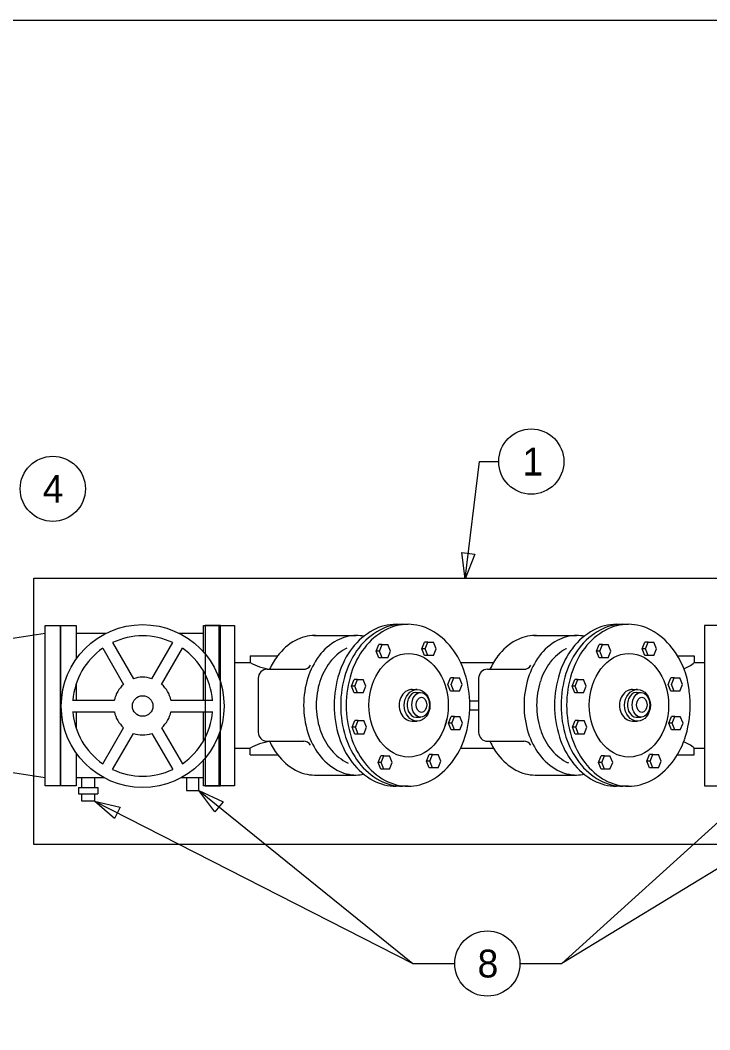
# Model space of a CAD drawing. Extents: x 10291.2 to 10382.2, y 10083.1 to 10135.3.
# Drawn here: x 10345.72 to 10363.56, y 10109.18 to 10135.29 of the extents above; entities that cross this region are included whole.
import ezdxf

# ---------------------------------------------------------------- set-up
doc = ezdxf.new("R2010")
doc.units = 0
for name, color, linetype in [('G-ANNO-NPLT', 7, 'Continuous'), ('G-ANNO-SYMB', 7, 'Continuous'), ('G-DETL-LINE', 7, 'Continuous'), ('G-DETL-TEXT', 7, 'Continuous')]:
    doc.layers.add(name, color=color, linetype=linetype)

msp = doc.modelspace()

# ---------------------------------------------------------------- linework, layer by layer
at = {"layer": 'G-ANNO-NPLT'}
msp.add_lwpolyline([(10336.657, 10086.15), (10336.657, 10135.292), (10382.157, 10135.292), (10382.157, 10086.15)], close=True, dxfattribs=at)
at = {"layer": 'G-ANNO-SYMB'}
for centre in [(10358.941, 10123.878), (10346.562, 10123.174), (10357.804, 10110.897)]:
    msp.add_circle(centre, 0.843, dxfattribs=at)
at = {"layer": 'G-DETL-LINE'}
for p, q in [((10355.441, 10119.67), (10355.753, 10119.67)), ((10361.142, 10119.67), (10361.453, 10119.67)), ((10363.422, 10119.612), (10363.422, 10117.576)), ((10346.364, 10119.436), (10344.045, 10119.066)), ((10347.94, 10119.436), (10347.165, 10119.436)), ((10350.463, 10119.436), (10349.833, 10119.436)), ((10353.303, 10119.379), (10354.412, 10119.379)), ((10359.004, 10119.379), (10360.113, 10119.379)), ((10348.106, 10119.201), (10348.647, 10118.264)), ((10349.126, 10118.264), (10349.667, 10119.201)), ((10354.928, 10118.974), (10354.997, 10119.148)), ((10355.081, 10119.148), (10354.997, 10119.148)), ((10355.012, 10118.974), (10355.081, 10119.148)), ((10355.081, 10119.148), (10355.226, 10119.148)), ((10355.296, 10118.974), (10355.226, 10119.148)), ((10356.11, 10119.035), (10356.18, 10119.209)), ((10356.264, 10119.209), (10356.18, 10119.209)), ((10356.195, 10119.035), (10356.264, 10119.209)), ((10356.264, 10119.209), (10356.409, 10119.209)), ((10356.479, 10119.035), (10356.409, 10119.209)), ((10360.628, 10118.974), (10360.698, 10119.148)), ((10360.782, 10119.148), (10360.698, 10119.148)), ((10360.713, 10118.974), (10360.782, 10119.148)), ((10360.782, 10119.148), (10360.927, 10119.148)), ((10360.997, 10118.974), (10360.927, 10119.148)), ((10361.811, 10119.035), (10361.88, 10119.209)), ((10361.964, 10119.209), (10361.88, 10119.209)), ((10361.895, 10119.035), (10361.964, 10119.209)), ((10361.964, 10119.209), (10362.109, 10119.209)), ((10362.18, 10119.035), (10362.109, 10119.209)), ((10347.853, 10119.054), (10348.394, 10118.117)), ((10349.379, 10118.117), (10349.92, 10119.054)), ((10351.667, 10118.856), (10352.38, 10118.856)), ((10351.667, 10118.856), (10351.667, 10118.681)), ((10355.012, 10118.974), (10354.928, 10118.974)), ((10354.997, 10118.8), (10354.928, 10118.974)), ((10355.081, 10118.8), (10355.012, 10118.974)), ((10355.226, 10118.799), (10355.296, 10118.974)), ((10356.195, 10119.035), (10356.11, 10119.035)), ((10356.18, 10118.861), (10356.11, 10119.035)), ((10356.264, 10118.861), (10356.18, 10118.861)), ((10356.264, 10118.861), (10356.195, 10119.035)), ((10356.409, 10118.86), (10356.264, 10118.861)), ((10356.409, 10118.86), (10356.479, 10119.035)), ((10360.698, 10118.8), (10360.628, 10118.974)), ((10360.713, 10118.974), (10360.628, 10118.974)), ((10360.782, 10118.8), (10360.713, 10118.974)), ((10360.927, 10118.799), (10360.997, 10118.974)), ((10361.88, 10118.861), (10361.811, 10119.035)), ((10361.895, 10119.035), (10361.811, 10119.035)), ((10361.964, 10118.861), (10361.88, 10118.861)), ((10361.964, 10118.861), (10361.895, 10119.035)), ((10362.109, 10118.86), (10361.964, 10118.861)), ((10362.109, 10118.86), (10362.18, 10119.035)), ((10362.718, 10118.856), (10363.154, 10118.856)), ((10362.72, 10118.856), (10363.155, 10118.856)), ((10363.154, 10118.856), (10363.154, 10118.682)), ((10363.155, 10118.856), (10363.155, 10118.681)), ((10351.265, 10118.681), (10351.667, 10118.681)), ((10355.081, 10118.8), (10354.997, 10118.8)), ((10355.226, 10118.799), (10355.081, 10118.8)), ((10357.113, 10118.681), (10357.963, 10118.681)), ((10360.782, 10118.8), (10360.698, 10118.8)), ((10360.927, 10118.799), (10360.782, 10118.799)), ((10363.155, 10118.681), (10363.422, 10118.681)), ((10352.111, 10118.507), (10353.056, 10118.507)), ((10356.784, 10118.114), (10356.853, 10118.288)), ((10356.937, 10118.288), (10356.853, 10118.288)), ((10356.868, 10118.114), (10356.937, 10118.288)), ((10356.937, 10118.288), (10357.082, 10118.288)), ((10357.152, 10118.114), (10357.082, 10118.288)), ((10357.812, 10118.507), (10358.757, 10118.507)), ((10362.485, 10118.114), (10362.554, 10118.288)), ((10362.638, 10118.288), (10362.554, 10118.288)), ((10362.569, 10118.114), (10362.638, 10118.288)), ((10362.638, 10118.288), (10362.783, 10118.288)), ((10362.853, 10118.114), (10362.783, 10118.288)), ((10351.879, 10118.274), (10351.879, 10116.878)), ((10354.293, 10118.072), (10354.362, 10118.246)), ((10354.362, 10117.897), (10354.293, 10118.072)), ((10354.377, 10118.072), (10354.293, 10118.072)), ((10354.446, 10118.246), (10354.362, 10118.246)), ((10354.377, 10118.072), (10354.446, 10118.246)), ((10354.446, 10117.897), (10354.377, 10118.072)), ((10354.446, 10118.246), (10354.591, 10118.246)), ((10354.662, 10118.072), (10354.591, 10118.246)), ((10354.591, 10117.897), (10354.662, 10118.072)), ((10356.853, 10117.94), (10356.784, 10118.114)), ((10356.937, 10117.94), (10356.868, 10118.114)), ((10357.082, 10117.939), (10357.152, 10118.114)), ((10357.579, 10118.274), (10357.579, 10116.878)), ((10359.994, 10118.072), (10360.063, 10118.246)), ((10360.063, 10117.897), (10359.994, 10118.072)), ((10360.078, 10118.072), (10359.994, 10118.072)), ((10360.147, 10118.246), (10360.063, 10118.246)), ((10360.078, 10118.072), (10360.147, 10118.246)), ((10360.147, 10117.897), (10360.078, 10118.072)), ((10360.147, 10118.246), (10360.292, 10118.246)), ((10360.362, 10118.072), (10360.292, 10118.246)), ((10360.292, 10117.897), (10360.362, 10118.072)), ((10362.554, 10117.94), (10362.485, 10118.114)), ((10362.638, 10117.94), (10362.569, 10118.114)), ((10362.783, 10117.939), (10362.853, 10118.114)), ((10354.446, 10117.897), (10354.362, 10117.897)), ((10354.591, 10117.897), (10354.446, 10117.897)), ((10355.855, 10117.983), (10355.987, 10117.983)), ((10355.955, 10117.907), (10356.078, 10117.907)), ((10356.937, 10117.94), (10356.853, 10117.94)), ((10357.082, 10117.939), (10356.937, 10117.94)), ((10360.147, 10117.897), (10360.063, 10117.897)), ((10360.292, 10117.897), (10360.147, 10117.897)), ((10361.556, 10117.983), (10361.688, 10117.983)), ((10361.655, 10117.907), (10361.779, 10117.907)), ((10362.638, 10117.94), (10362.554, 10117.94)), ((10362.783, 10117.939), (10362.638, 10117.94)), ((10347.072, 10117.706), (10348.155, 10117.706)), ((10349.618, 10117.706), (10350.701, 10117.706)), ((10357.349, 10117.692), (10357.579, 10117.692)), ((10347.072, 10117.407), (10348.155, 10117.407)), ((10349.618, 10117.407), (10350.701, 10117.407)), ((10355.955, 10117.267), (10356.078, 10117.267)), ((10356.797, 10117.115), (10356.866, 10117.289)), ((10356.95, 10117.289), (10356.866, 10117.289)), ((10356.881, 10117.115), (10356.95, 10117.289)), ((10356.95, 10117.289), (10357.095, 10117.289)), ((10357.165, 10117.115), (10357.095, 10117.289)), ((10357.349, 10117.46), (10357.579, 10117.46)), ((10361.655, 10117.267), (10361.779, 10117.267)), ((10362.497, 10117.115), (10362.567, 10117.289)), ((10362.651, 10117.289), (10362.567, 10117.289)), ((10362.582, 10117.115), (10362.651, 10117.289)), ((10362.651, 10117.289), (10362.796, 10117.289)), ((10362.866, 10117.115), (10362.796, 10117.289)), ((10347.853, 10116.059), (10348.394, 10116.996)), ((10349.379, 10116.996), (10349.92, 10116.059)), ((10354.307, 10117.007), (10354.377, 10117.181)), ((10354.392, 10117.007), (10354.307, 10117.007)), ((10354.377, 10116.833), (10354.307, 10117.007)), ((10354.461, 10117.181), (10354.377, 10117.181)), ((10354.392, 10117.007), (10354.461, 10117.181)), ((10354.461, 10116.833), (10354.392, 10117.007)), ((10354.461, 10117.181), (10354.606, 10117.181)), ((10354.676, 10117.007), (10354.606, 10117.181)), ((10354.606, 10116.832), (10354.676, 10117.007)), ((10355.855, 10117.169), (10355.987, 10117.169)), ((10356.881, 10117.115), (10356.797, 10117.115)), ((10356.866, 10116.941), (10356.797, 10117.115)), ((10356.95, 10116.941), (10356.881, 10117.115)), ((10357.095, 10116.94), (10357.165, 10117.115)), ((10360.008, 10117.007), (10360.077, 10117.181)), ((10360.092, 10117.007), (10360.008, 10117.007)), ((10360.077, 10116.833), (10360.008, 10117.007)), ((10360.162, 10117.181), (10360.077, 10117.181)), ((10360.092, 10117.007), (10360.162, 10117.181)), ((10360.162, 10116.833), (10360.092, 10117.007)), ((10360.162, 10117.181), (10360.307, 10117.181)), ((10360.377, 10117.007), (10360.307, 10117.181)), ((10360.307, 10116.832), (10360.377, 10117.007)), ((10361.556, 10117.169), (10361.688, 10117.169)), ((10362.582, 10117.115), (10362.497, 10117.115)), ((10362.567, 10116.941), (10362.497, 10117.115)), ((10362.651, 10116.941), (10362.582, 10117.115)), ((10362.796, 10116.94), (10362.866, 10117.115)), ((10348.106, 10115.912), (10348.647, 10116.849)), ((10349.126, 10116.849), (10349.667, 10115.912)), ((10354.461, 10116.833), (10354.377, 10116.833)), ((10354.606, 10116.832), (10354.461, 10116.833)), ((10356.95, 10116.941), (10356.866, 10116.941)), ((10357.095, 10116.94), (10356.95, 10116.941)), ((10360.162, 10116.833), (10360.077, 10116.833)), ((10360.307, 10116.832), (10360.162, 10116.833)), ((10362.651, 10116.941), (10362.567, 10116.941)), ((10362.796, 10116.94), (10362.651, 10116.941)), ((10351.265, 10116.471), (10351.667, 10116.471)), ((10351.667, 10116.296), (10351.667, 10116.471)), ((10352.111, 10116.645), (10353.056, 10116.645)), ((10357.113, 10116.471), (10357.963, 10116.471)), ((10357.812, 10116.645), (10358.757, 10116.645)), ((10363.155, 10116.296), (10363.155, 10116.471)), ((10363.155, 10116.471), (10363.422, 10116.471)), ((10351.667, 10116.296), (10352.38, 10116.296)), ((10354.977, 10116.097), (10355.046, 10116.271)), ((10355.13, 10116.271), (10355.046, 10116.271)), ((10355.061, 10116.097), (10355.13, 10116.271)), ((10355.13, 10116.271), (10355.275, 10116.27)), ((10355.345, 10116.097), (10355.275, 10116.27)), ((10356.231, 10116.133), (10356.3, 10116.307)), ((10356.384, 10116.307), (10356.3, 10116.307)), ((10356.315, 10116.133), (10356.384, 10116.307)), ((10356.384, 10116.307), (10356.529, 10116.307)), ((10356.599, 10116.133), (10356.529, 10116.307)), ((10360.677, 10116.097), (10360.746, 10116.271)), ((10360.831, 10116.271), (10360.746, 10116.271)), ((10360.762, 10116.097), (10360.831, 10116.271)), ((10360.831, 10116.271), (10360.976, 10116.27)), ((10361.046, 10116.097), (10360.976, 10116.27)), ((10361.932, 10116.133), (10362.001, 10116.307)), ((10362.085, 10116.307), (10362.001, 10116.307)), ((10362.016, 10116.133), (10362.085, 10116.307)), ((10362.085, 10116.307), (10362.23, 10116.307)), ((10362.3, 10116.133), (10362.23, 10116.307)), ((10362.72, 10116.296), (10363.155, 10116.296)), ((10346.364, 10115.696), (10344.045, 10116.066)), ((10355.061, 10116.097), (10354.977, 10116.097)), ((10355.046, 10115.922), (10354.977, 10116.097)), ((10355.13, 10115.922), (10355.061, 10116.097)), ((10355.275, 10115.922), (10355.345, 10116.097)), ((10356.315, 10116.133), (10356.231, 10116.133)), ((10356.3, 10115.959), (10356.231, 10116.133)), ((10356.384, 10115.959), (10356.3, 10115.959)), ((10356.384, 10115.959), (10356.315, 10116.133)), ((10356.529, 10115.958), (10356.384, 10115.959)), ((10356.529, 10115.958), (10356.599, 10116.133)), ((10360.746, 10115.922), (10360.677, 10116.097)), ((10360.762, 10116.097), (10360.677, 10116.097)), ((10360.831, 10115.922), (10360.762, 10116.097)), ((10360.976, 10115.922), (10361.046, 10116.097)), ((10362.001, 10115.959), (10361.932, 10116.133)), ((10362.016, 10116.133), (10361.932, 10116.133)), ((10362.085, 10115.959), (10362.001, 10115.959)), ((10362.085, 10115.959), (10362.016, 10116.133)), ((10362.23, 10115.958), (10362.085, 10115.959)), ((10362.23, 10115.958), (10362.3, 10116.133)), ((10347.903, 10115.696), (10347.165, 10115.696)), ((10347.314, 10115.453), (10347.314, 10115.696)), ((10347.64, 10115.696), (10347.64, 10115.453)), ((10350.463, 10115.696), (10349.871, 10115.696)), ((10350.019, 10115.696), (10350.019, 10115.37)), ((10350.344, 10115.37), (10350.344, 10115.696)), ((10353.337, 10115.773), (10354.412, 10115.773)), ((10355.13, 10115.922), (10355.046, 10115.922)), ((10355.275, 10115.922), (10355.13, 10115.922)), ((10359.038, 10115.773), (10360.113, 10115.773)), ((10360.831, 10115.922), (10360.746, 10115.922)), ((10360.976, 10115.922), (10360.831, 10115.922)), ((10347.226, 10115.453), (10347.728, 10115.453)), ((10347.226, 10115.453), (10347.226, 10115.285)), ((10347.226, 10115.453), (10347.226, 10115.453)), ((10347.728, 10115.453), (10347.728, 10115.285)), ((10347.728, 10115.453), (10347.728, 10115.453)), ((10355.753, 10115.482), (10355.441, 10115.482)), ((10361.453, 10115.482), (10361.142, 10115.482)), ((10347.226, 10115.285), (10347.728, 10115.285)), ((10347.226, 10115.285), (10347.226, 10115.285)), ((10347.314, 10115.1), (10347.314, 10115.285)), ((10347.64, 10115.285), (10347.64, 10115.1)), ((10347.728, 10115.285), (10347.728, 10115.285)), ((10350.019, 10115.37), (10350.344, 10115.37)), ((10347.64, 10115.1), (10347.314, 10115.1))]:
    msp.add_line(p, q, dxfattribs=at)
for points in [[(10346.364, 10119.639), (10346.765, 10119.639), (10346.765, 10115.494), (10346.364, 10115.494)], [(10350.903, 10119.639), (10350.503, 10119.639), (10350.503, 10115.494), (10350.903, 10115.494)]]:
    msp.add_lwpolyline(points, close=True, dxfattribs=at)
for points in [[(10347.165, 10116.346), (10347.165, 10115.494), (10346.765, 10115.494), (10346.765, 10119.639), (10347.165, 10119.639), (10347.165, 10118.767)], [(10350.463, 10118.951), (10350.463, 10119.639), (10350.864, 10119.639), (10350.864, 10118.277)], [(10350.864, 10118.277), (10350.864, 10119.639), (10351.265, 10119.639), (10351.265, 10115.494), (10350.864, 10115.494), (10350.864, 10116.836)], [(10363.823, 10118.277), (10363.823, 10119.639), (10363.422, 10119.639), (10363.422, 10115.494), (10363.823, 10115.494), (10363.823, 10116.836)], [(10350.463, 10117.706), (10350.463, 10118.453)], [(10347.165, 10118.129), (10347.165, 10117.706)], [(10347.165, 10117.407), (10347.165, 10116.984)], [(10350.463, 10116.66), (10350.463, 10117.407)], [(10350.864, 10116.836), (10350.864, 10115.494), (10350.463, 10115.494), (10350.463, 10116.162)]]:
    msp.add_lwpolyline(points, dxfattribs=at)
for radius in [2.105, 0.265]:
    msp.add_circle((10348.887, 10117.557), radius, dxfattribs=at)
for centre, radius, start, end in [((10355.441, 10118.436), 1.234, 90, 118.4823), ((10355.609, 10118.436), 1.234, 90, 118.4823), ((10355.753, 10118.436), 1.234, 90, 118.4823), ((10355.753, 10118.436), 1.234, 61.5177, 90), ((10361.142, 10118.436), 1.234, 90, 118.4823), ((10361.31, 10118.436), 1.234, 90, 118.4823), ((10361.453, 10118.436), 1.234, 90, 118.4823), ((10361.453, 10118.436), 1.234, 61.5177, 90), ((10348.887, 10117.557), 1.814, 64.6295, 115.3705), ((10353.337, 10118.343), 1.036, 90, 118.7905), ((10353.337, 10118.343), 1.036, 88.161, 90), ((10354.412, 10118.343), 1.036, 90, 118.7905), ((10355.666, 10118.022), 1.705, 118.4823, 142.6401), ((10354.412, 10118.343), 1.036, 79.0253, 90), ((10355.834, 10118.022), 1.705, 118.4823, 142.6401), ((10355.977, 10118.022), 1.705, 118.4823, 142.6401), ((10355.528, 10118.022), 1.705, 37.3599, 61.5177), ((10359.038, 10118.343), 1.036, 90, 118.7905), ((10359.038, 10118.343), 1.036, 88.161, 90), ((10360.113, 10118.343), 1.036, 90, 118.7905), ((10361.366, 10118.022), 1.705, 118.4823, 142.6401), ((10360.113, 10118.343), 1.036, 79.0253, 90), ((10361.534, 10118.022), 1.705, 118.4823, 142.6401), ((10361.678, 10118.022), 1.705, 118.4823, 142.6401), ((10361.229, 10118.022), 1.705, 37.3599, 61.5177), ((10353.54, 10117.974), 1.458, 118.7905, 142.993), ((10354.615, 10117.974), 1.458, 118.7905, 142.993), ((10359.241, 10117.974), 1.458, 118.7905, 142.993), ((10360.315, 10117.974), 1.458, 118.7905, 142.993), ((10348.887, 10117.557), 1.814, 124.6295, 175.2858), ((10348.887, 10117.557), 1.814, 4.7142, 55.3705), ((10353.859, 10117.733), 1.857, 142.993, 155.3864), ((10354.934, 10117.733), 1.857, 142.993, 162.661), ((10354.745, 10117.913), 1.277, 118.54, 142.7064), ((10356.019, 10117.752), 2.15, 142.6401, 162.4514), ((10354.575, 10118.225), 0.921, 116.0419, 118.54), ((10356.187, 10117.752), 2.15, 142.6401, 162.4514), ((10356.331, 10117.752), 2.15, 142.6401, 162.4514), ((10355.174, 10117.752), 2.15, 17.5486, 37.3599), ((10359.56, 10117.733), 1.857, 142.993, 155.3864), ((10360.635, 10117.733), 1.857, 142.993, 162.661), ((10360.446, 10117.913), 1.277, 118.54, 142.7064), ((10361.72, 10117.752), 2.15, 142.6401, 162.4514), ((10360.276, 10118.225), 0.921, 117.1537, 118.54), ((10361.888, 10117.752), 2.15, 142.6401, 162.4514), ((10362.032, 10117.752), 2.15, 142.6401, 162.4514), ((10360.877, 10117.735), 2.159, 6.534, 37.7579), ((10352.451, 10120.138), 1.655, 241.7189, 260.4318), ((10353.048, 10118.713), 0.206, 267.8882, 330.0944), ((10355.013, 10117.709), 1.613, 142.7064, 162.4909), ((10358.749, 10118.713), 0.206, 267.8882, 330.0944), ((10360.713, 10117.709), 1.613, 142.7064, 162.4909), ((10362.707, 10119.156), 0.652, 285.3257, 313.3274), ((10362.708, 10119.155), 0.651, 285.3257, 313.3274), ((10348.887, 10117.557), 0.746, 71.3127, 108.6873), ((10352.111, 10118.274), 0.233, 90, 180), ((10355.437, 10117.576), 2.385, 162.661, 180), ((10356.576, 10117.576), 2.734, 162.4514, 180), ((10356.744, 10117.576), 2.734, 162.4514, 180), ((10356.888, 10117.576), 2.734, 162.4514, 180), ((10354.617, 10117.576), 2.734, 0, 17.5486), ((10357.812, 10118.274), 0.233, 90, 180), ((10361.138, 10117.576), 2.385, 162.661, 180), ((10362.277, 10117.576), 2.734, 162.4514, 180), ((10362.445, 10117.576), 2.734, 162.4514, 180), ((10362.589, 10117.576), 2.734, 162.4514, 180), ((10348.887, 10117.557), 0.746, 131.3127, 168.4779), ((10348.887, 10117.557), 0.746, 11.5221, 48.6873), ((10355.434, 10117.576), 2.056, 162.4909, 180), ((10361.135, 10117.576), 2.056, 162.4909, 180), ((10355.855, 10117.71), 0.273, 90, 116.9105), ((10355.987, 10117.71), 0.273, 90, 116.9105), ((10361.556, 10117.71), 0.273, 90, 116.9105), ((10361.688, 10117.71), 0.273, 90, 116.9105), ((10360.318, 10117.576), 2.734, 0, 8.5788), ((10355.437, 10117.576), 2.385, 180, 197.339), ((10355.434, 10117.576), 2.056, 180, 197.5091), ((10356.576, 10117.576), 2.734, 180, 197.5486), ((10356.744, 10117.576), 2.734, 180, 197.5486), ((10356.888, 10117.576), 2.734, 180, 197.5486), ((10354.617, 10117.576), 2.734, 342.4514, 0), ((10361.138, 10117.576), 2.385, 180, 197.339), ((10361.135, 10117.576), 2.056, 180, 197.5091), ((10362.277, 10117.576), 2.734, 180, 197.5486), ((10362.445, 10117.576), 2.734, 180, 197.5486), ((10362.589, 10117.576), 2.734, 180, 197.5486), ((10360.318, 10117.576), 2.734, 341.1333, 0), ((10348.887, 10117.557), 1.814, 184.7142, 235.3705), ((10348.887, 10117.557), 0.746, 191.5221, 228.6873), ((10348.887, 10117.557), 0.746, 311.3127, 348.4779), ((10348.887, 10117.557), 1.814, 304.6295, 355.2858), ((10355.051, 10117.576), 1.741, 342.3955, 348.0705), ((10348.887, 10117.557), 0.746, 251.3127, 288.6873), ((10352.111, 10116.878), 0.233, 180, 270), ((10354.934, 10117.419), 1.857, 197.339, 217.007), ((10355.013, 10117.443), 1.613, 197.5091, 217.2936), ((10356.019, 10117.4), 2.15, 197.5486, 217.3599), ((10356.187, 10117.4), 2.15, 197.5486, 217.3599), ((10356.331, 10117.4), 2.15, 197.5486, 217.3599), ((10355.174, 10117.4), 2.15, 322.6401, 342.4514), ((10357.812, 10116.878), 0.233, 180, 270), ((10360.635, 10117.419), 1.857, 197.339, 217.007), ((10360.713, 10117.443), 1.613, 197.5091, 217.2936), ((10361.72, 10117.4), 2.15, 197.5486, 217.3599), ((10361.888, 10117.4), 2.15, 197.5486, 217.3599), ((10362.032, 10117.4), 2.15, 197.5486, 217.3599), ((10352.451, 10115.013), 1.655, 99.5682, 118.2811), ((10353.859, 10117.419), 1.857, 204.6136, 217.007), ((10353.048, 10116.439), 0.206, 29.9056, 92.1118), ((10354.745, 10117.239), 1.277, 217.2936, 241.46), ((10359.56, 10117.419), 1.857, 204.6136, 217.007), ((10358.749, 10116.439), 0.206, 29.9056, 92.1118), ((10360.446, 10117.239), 1.277, 217.2936, 241.46), ((10360.875, 10117.4), 2.15, 322.6401, 340.5399), ((10362.708, 10115.997), 0.651, 46.6726, 74.6743), ((10353.54, 10117.178), 1.458, 217.007, 241.2095), ((10354.615, 10117.178), 1.458, 217.007, 241.2095), ((10359.241, 10117.178), 1.458, 217.007, 241.2095), ((10360.315, 10117.178), 1.458, 217.007, 241.2095), ((10354.575, 10116.926), 0.921, 241.46, 246.2039), ((10355.666, 10117.13), 1.705, 217.3599, 241.5177), ((10355.834, 10117.13), 1.705, 217.3599, 241.5177), ((10355.977, 10117.13), 1.705, 217.3599, 241.5177), ((10355.528, 10117.13), 1.705, 298.4823, 322.6401), ((10360.276, 10116.926), 0.921, 241.46, 246.0106), ((10361.366, 10117.13), 1.705, 217.3599, 241.5177), ((10361.534, 10117.13), 1.705, 217.3599, 241.5177), ((10361.678, 10117.13), 1.705, 217.3599, 241.5177), ((10361.229, 10117.13), 1.705, 298.4823, 322.6401), ((10348.887, 10117.557), 1.814, 244.6295, 295.3705), ((10353.337, 10116.809), 1.036, 241.2095, 270), ((10354.412, 10116.809), 1.036, 241.2095, 270), ((10354.412, 10116.809), 1.036, 270, 280.9747), ((10359.038, 10116.809), 1.036, 241.2095, 270), ((10360.113, 10116.809), 1.036, 241.2095, 270), ((10360.113, 10116.809), 1.036, 270, 280.9747), ((10355.441, 10116.716), 1.234, 241.5177, 270), ((10355.609, 10116.716), 1.234, 241.5177, 270), ((10355.753, 10116.716), 1.234, 241.5177, 270), ((10355.753, 10116.716), 1.234, 270, 298.4823), ((10361.142, 10116.716), 1.234, 241.5177, 270), ((10361.31, 10116.716), 1.234, 241.5177, 270), ((10361.453, 10116.716), 1.234, 241.5177, 270), ((10361.453, 10116.716), 1.234, 270, 298.4823)]:
    msp.add_arc(centre, radius, start, end, dxfattribs=at)
for centre, major_axis, ratio in [((10355.767, 10117.576), (0, 1.338), 0.766042), ((10361.467, 10117.576), (0, 1.338), 0.766042), ((10355.987, 10117.576), (0, 0.407), 0.816083), ((10356.078, 10117.587), (0, 0.32), 0.711467), ((10356.1, 10117.587), (0, 0.195), 0.69425), ((10361.688, 10117.576), (0, 0.407), 0.816083), ((10361.779, 10117.587), (0, 0.32), 0.711467), ((10361.8, 10117.587), (0, 0.195), 0.69425)]:
    msp.add_ellipse(centre, major_axis=major_axis, ratio=ratio, dxfattribs=at)
for centre, major_axis, ratio in [((10355.855, 10117.576), (0, 0.407), 0.816083), ((10355.955, 10117.587), (0, 0.32), 0.707873), ((10361.556, 10117.576), (0, 0.407), 0.816083), ((10361.655, 10117.587), (0, 0.32), 0.707873)]:
    msp.add_ellipse(centre, major_axis=major_axis, ratio=ratio, start_param=0, end_param=3.141593, dxfattribs=at)
at = {"layer": 'G-DETL-TEXT'}
for p, q in [((10357.23, 10120.843), (10357.598, 10123.878)), ((10357.598, 10123.878), (10358.098, 10123.878)), ((10350.344, 10115.37), (10355.879, 10110.897)), ((10367.072, 10115.37), (10359.729, 10110.897)), ((10347.64, 10115.1), (10355.879, 10110.897)), ((10364.368, 10115.1), (10359.729, 10110.897)), ((10355.879, 10110.897), (10356.961, 10110.897)), ((10358.647, 10110.897), (10359.729, 10110.897))]:
    msp.add_line(p, q, dxfattribs=at)
for points in [[(10357.476, 10121.485), (10357.23, 10120.843), (10357.145, 10121.525)], [(10346.072, 10120.859), (10368.384, 10120.859), (10368.384, 10113.973), (10346.072, 10113.973)], [(10350.758, 10114.822), (10350.344, 10115.37), (10350.967, 10115.081)], [(10348.158, 10114.648), (10347.64, 10115.1), (10348.309, 10114.945)]]:
    msp.add_lwpolyline(points, close=True, dxfattribs=at)

# ---------------------------------------------------------------- texts
at = {"layer": 'G-ANNO-SYMB'}
for s, p in [('1', (10358.71, 10123.518)), ('4', (10346.304, 10122.814)), ('8', (10357.551, 10110.537))]:
    msp.add_text(s, height=0.721, dxfattribs=at).set_placement(p)

doc.saveas('drawing.dxf')
